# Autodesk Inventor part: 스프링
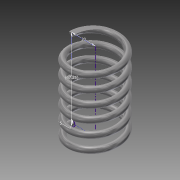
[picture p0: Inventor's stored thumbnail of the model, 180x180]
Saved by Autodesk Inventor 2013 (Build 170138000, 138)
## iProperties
Created: 2016-08
Part Number: 스프링
Material: 스테인리스강
Document SubType Name: Modeling
Designer: Administrator
Density: 8.08 g/cm^3
Mass: 117.728 g
Surface Area: 118.214 cm^2
Volume: 14.5703 cm^3
Author: Administrator
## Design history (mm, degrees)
sketch "스케치1"
  geometry: L1 (0, 0)-(20, 0); L2 (20, 0)-(20, 67.25); L3 (20, 67.25)-(0, 67.25); L4 (0, 67.25)-(0, 0); C1 r 2.5 at (20, 0)
  constraints: 8 end point, 2 parallel, 1 centre point, 1 coincident, 1 horizontal, 1 perpendicular
  dimensions: "d0" = 20 distance of L3.end L2.end; "d1" = 67.25 distance of L2.end L1.end (derived); "d2" = 5 diameter of C1
feature "코일1" sketch "스케치1" pitch "d3" = 10; turns "d5" = 6; dims "d4" = 67.25 (= d1), "d6" = 0, angle "d7" = 90 deg, angle "d8" = 90 deg, "d9" = 0, "d10" = 0
sketch "스케치2"
  geometry: L1 (-22.5, 0)-(-17.5, 0) reference; 1 further point
  constraints: 1 horizontal alignment
extrude "돌출1" cut sketch "스케치2" distance "d11" = 10; taper "d12" = 0 deg
node "작업 평면1"
sketch "스케치3"
  geometry: L1 (-17.5, 0)-(-22.5, 0) reference; 1 further point
  constraints: 1 horizontal alignment
extrude "돌출2" cut sketch "스케치3" distance "d14" = 10; taper "d15" = 0 deg
node "솔리드1"
node "절단 모서리 투영1"
node "절단 모서리 투영2"
other parameters: "d13" = 67.25 (= d1)
